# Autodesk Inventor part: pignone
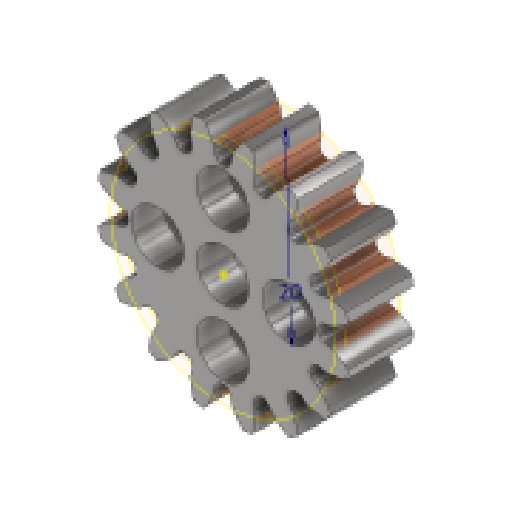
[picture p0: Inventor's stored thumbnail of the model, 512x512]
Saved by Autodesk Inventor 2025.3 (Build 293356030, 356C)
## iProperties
Created: 2025-12
Part Number: pignone
Material: Plastica ABS
Document SubType Name: Modeling
Designer: R5800u
Density: 1.06 g/cm^3
Appearance: Acciaio - Lucido
Author: R5800u
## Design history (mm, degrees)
sketch "Sketch1"
  geometry: C1 r 10.125 at (0, 0) reference; C2 r 11.276 at (0, 0) reference; C3 r 12 at (0, 0) reference; A1 r 13.5 centre (0, 0) between (-2.142, 13.329) and (2.142, 13.329) reference; 815 further points
  constraints: 4 centre point, 2 point on circle, 1769 other
  dimensions: "d4" = 360 deg dimension on point (0, 0) A1.start (derived)
  node "Schizzo - Serie circolare1" dims "d4" = 360 deg (derived)
extrude "Estrusione1" new body sketch "Sketch1" distance "d0" = 6; taper "d1" = 0 deg
extrude "Estrusione2" cut sketch "Sketch1" extent not by distance; stored distance "d6" = 0; taper "d7" = 0 deg
pattern_circular "Serie circolare1" dims angle "d9" = 360 deg
sketch "Schizzo2"
  geometry: A1 r 13.5 centre (0, 0) between (-11.495, -7.08) and (-10.94, -7.91) reference; 2 further points
  constraints: 1 coincident
hole "Foro1" sketch "Schizzo2" at (0, 0) diameter "d11" = 3.2; stored, may be unused: countersink angle "d15" = 90 deg, drill point angle "d17" = 118 deg; dims "d12" = 6, "d13" = 5.5, "d14" = 3.4, "d16" = 11
sketch "Schizzo3"
  geometry: C1 r 12 at (0, 0); 1 further point
  constraints: 1 centre point, 1 coincident
  dimensions: "d18" = 24 diameter of C1
feature "SupEstrusione1" sketch "Schizzo3" dims "d19" = 10, "d20" = 0
sketch "Schizzo4"
  geometry: C1 r 1.25 at (-4.578, -5.296) reference; C2 r 1.25 at (-5.296, 4.578) reference; C3 r 1.25 at (4.578, 5.296) reference; C4 r 1.25 at (5.296, -4.578) reference; 1 further point
hole "Foro2" sketch "Schizzo4" at (-4.578, -5.296), (-5.296, 4.578), (4.578, 5.296), (5.296, -4.578) diameter "d21" = 3.2; stored, may be unused: countersink angle "d25" = 90 deg, drill point angle "d27" = 118 deg; dims "d22" = 6, "d23" = 5.5, "d24" = 3.4, "d26" = 8
sketch "Schizzo5"
  geometry: C1 r 1.6 at (0, 0) reference; 2 further points
  constraints: 1 coincident
hole "Foro3" sketch "Schizzo5" at (0, 0) diameter "d28" = 3.2; stored, may be unused: countersink angle "d32" = 90 deg, drill point angle "d34" = 118 deg; dims "d29" = 6, "d30" = 6.5, "d31" = 3.4, "d33" = 11
sketch "Schizzo6"
  geometry: C1 r 2.75 at (0, 0) reference; A1 r 13.5 centre (0, 0) between (3.122, 13.134) and (2.142, 13.329) reference; A2 r 13.5 centre (0, 0) between (-2.142, 13.329) and (-3.122, 13.134) reference; A3 r 13.5 centre (0, 0) between (-7.08, 11.495) and (-7.91, 10.94) reference; A4 r 13.5 centre (0, 0) between (-10.94, 7.91) and (-11.495, 7.08) reference; A5 r 13.5 centre (0, 0) between (-13.134, 3.122) and (-13.329, 2.142) reference; A6 r 13.5 centre (0, 0) between (-13.329, -2.142) and (-13.134, -3.122) reference; A7 r 13.5 centre (0, 0) between (-11.495, -7.08) and (-10.94, -7.91) reference; A8 r 13.5 centre (0, 0) between (-7.91, -10.94) and (-7.08, -11.495) reference; A9 r 13.5 centre (0, 0) between (-3.122, -13.134) and (-2.142, -13.329) reference; A10 r 13.5 centre (0, 0) between (2.142, -13.329) and (3.122, -13.134) reference; A11 r 13.5 centre (0, 0) between (7.08, -11.495) and (7.91, -10.94) reference; A12 r 13.5 centre (0, 0) between (10.94, -7.91) and (11.495, -7.08) reference; A13 r 13.5 centre (0, 0) between (13.134, -3.122) and (13.329, -2.142) reference; A14 r 13.5 centre (0, 0) between (13.329, 2.142) and (13.134, 3.122) reference; A15 r 13.5 centre (0, 0) between (11.495, 7.08) and (10.94, 7.91) reference; A16 r 13.5 centre (0, 0) between (7.91, 10.94) and (7.08, 11.495) reference; 33 further points
  constraints: 2 horizontal alignment, 2 vertical alignment, 44 other
extrude "Estrusione3" join sketch "Schizzo6" distance "d35" = 1; taper "d36" = 0 deg
sketch "Schizzo7"
  geometry: 1 further point
sketch "Schizzo10"
  geometry: C1 r 3.25 at (0, 0) reference; C2 r 12 at (0, 0); 1 further point
  constraints: 1 centre point, 1 coincident
  dimensions: "d47" = 24 diameter of C2
feature "SupEstrusione2" sketch "Schizzo10" dims "d48" = 10, "d49" = 0
sketch "Schizzo11"
  geometry: C1 r 1.6 at (0, 0) reference; C2 r 10 at (0, 0); 1 further point
  constraints: 1 centre point, 1 coincident
  dimensions: "d50" = 20 diameter of C2
sketch "Schizzo12"
  geometry: L1 (0, 0)-(0, 7)
  constraints: 2 end point, 1 vertical
  dimensions: "d51" = 7 distance of L1.start L1.end
hole "Foro5" sketch "Schizzo12" at (0, 7) diameter "d52" = 3.2; stored, may be unused: countersink angle "d56" = 90 deg, drill point angle "d58" = 118 deg; dims "d53" = 6, "d54" = 5.6, "d55" = 3.4, "d57" = 8
pattern_circular "Serie circolare2" dims angle "d60" = 360 deg
node "Solido1"
node "Superf1"
node "Riferimento1"
node "Riferimento2"
node "Riferimento3"
node "Riferimento4"
node "Linea chiusa proiettata1"
node "Superf2"
other parameters: "Modulo" = 1.5 [user parameter], "Angolo_di_pressione" = 20 deg [user parameter], "Gioco_profilo_unità" = 2.5 [user parameter], "Raggio_circolare_unità" = 3.5 [user parameter], "Diametro_testa" = 27 [user parameter], "Diametro_di_fondo" = 20.25 [user parameter], "Diametro_di_base" = 22.55262 [user parameter], "Diametro_primitivo" = 24 [user parameter], "Angolo_elica" = 0 [user parameter], "Correzione_unità" = 0 [user parameter], "Modifica_aggiunta_unità" = 0 [user parameter], "Passo_circonferenziale" = 27 deg [user parameter], "Spostamento_strumento_gioco" = 0 [user parameter], "Spostamento_strumento_totale" = 0 [user parameter], "Interno" = 0 [user parameter]
